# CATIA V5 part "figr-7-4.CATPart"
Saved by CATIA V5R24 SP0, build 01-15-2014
Part number: Part1
Bounding box of the stored display mesh (mm): x -20 to 20, y -95 to 0, z 0 to 40
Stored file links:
  D:\KAVITA\CATIA V5-6R2014 Project_ Kavita\CATIA V5-6R2014_partfiles\Partfiles\c07_catia_v5-6r2014_prt\figr-7-4.CATPart
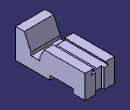
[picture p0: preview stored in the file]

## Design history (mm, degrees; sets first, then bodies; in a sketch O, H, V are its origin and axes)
Body1 (main body)
  Sketch1 on yz-plane, origin (0, 0, 0), H (0, 1, 0), V (0, 0, 1)
    line L1 (0, 0) -> (-16, 0)
    line L2 (-16, 0) -> (-16, 6)
    line L3 (-16, 6) -> (-48, 6)
    line L4 (-48, 6) -> (-48, 0)
    point P4 (-48, 0)
    line L5 (-48, 0) -> (-95, 0)
    line L6 (-95, 0) -> (-95, 40)
    line L7 (-95, 40) -> (-83, 40)
    line L8 (-83, 40) -> (-74, 20)
    line L9 (-74, 20) -> (-74, 16)
    line L10 (-74, 16) -> (-62, 16)
    line L11 (-62, 16) -> (-62, 20)
    line L12 (-62, 20) -> (-56, 32)
    line L13 (-56, 32) -> (0, 32)
    line L14 (0, 32) -> (0, 0)
    length L1 = 16
    length L3 = 32
    length L13 = 56
    distance L14 L6 = 95
    length L14 = 32
    length L6 = 40
    length L12 H = 6
    length L10 = 12
    length L7 = 12
    length L9 = 4
    length L2 = 6
    distance L10 L5 = 16
    length L12 V = 12
    horizontal: L1 H, L3 H, L5 H, L7 H, L10 H, L13 H
    vertical: L2 V, L4 V, L6 V, L9 V, L11 V, L14 V
    coincidence: P4 H
  Pad1: profile Sketch1, direction (1, 0, 0), length 20, mirrored extent
  Sketch2 on face of Pad1, origin (0, 0, 0), H (-1, 0, 0), V (0, 0, 1)
    axis line L1 (0, 0) -> (0, 40.9766)
    point P2 (0, 32)
    line L2 (0, 32) -> (-8, 32)
    point P3 (-8, 32)
    line L3 (-8, 32) -> (-12, 26)
    point P4 (-12, 26)
    line L4 (-12, 26) -> (0, 26)
    point P5 (0, 26)
    reference projected line E1 (-20, 32) -> (20, 32) from edge [face of Pad1 | face of Pad1]
    point P6 (0, 32)
    point P7 (8, 32)
    point P8 (12, 26)
    point P9 (0, 26)
    line L5 (0, 32) -> (8, 32)
    line L6 (8, 32) -> (12, 26)
    line L7 (12, 26) -> (0, 26)
    reference projected line E2 (-20, 0) -> (-20, 32) from edge [face of Pad1 | face of Pad1]
    reference projected line E3 (-20, 20) -> (-20, 40) from edge [face of Pad1 | face of Pad1]
    distance P4 E2 = 8
    length L3 V = 6
    distance P3 E3 = 12
    vertical: L1 V
    coincidence: P2 L1, P5 L1, L2 E1, P2 P6, P5 P9
    horizontal: L2 H, L4 H
    symmetry: P2 P6 L1, P3 P7 L1, P4 P8 L1, P5 P9 L1, L2 L5 L1, L3 L6 L1, L4 L7 L1
  Pocket1: profile Sketch2, direction (0, -1, 0), through (limit type 6)
  Sketch3 on face of Pad1, origin (0, 0, 0), H (-1, 0, 0), V (0, 0, 1)
    line L1 (-6, 0) -> (6, 0)
    line L2 (6, 0) -> (6, 26)
    line L3 (6, 26) -> (-6, 26)
    line L4 (-6, 26) -> (-6, 0)
    reference projected line E1 (-12, 26) -> (0, 26) from edge [face of Pad1 | face of Pocket1]
    length L1 = 12
    horizontal: L1 H, L3 H
    vertical: L2 V, L4 V
    midpoint: O L1
    coincidence: L3 E1
  Pocket2: profile Sketch3, direction (0, -1, 0), length 4
  Sketch4 "Sketch.4" on face of Pad1, origin (0, 0, 40), H (1, 0, 0), V (0, 1, 0)
    line L1 (-12.5, -95) -> (12.5, -95)
    line L2 (12.5, -95) -> (12.5, -92)
    line L3 (12.5, -92) -> (-12.5, -92)
    line L4 (-12.5, -92) -> (-12.5, -95)
    reference projected line E1 (-20, -95) -> (20, -95) from edge [face of Pad1 | face of Pad1]
    axis line L5 (0, 0) -> (0, -95)
    point P5 (0, -95)
    length L1 = 25
    length L2 = 3
    horizontal: L1 H, L3 H
    vertical: L2 V, L4 V, L5 V
    coincidence: L1 E1
    midpoint: P5 L1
